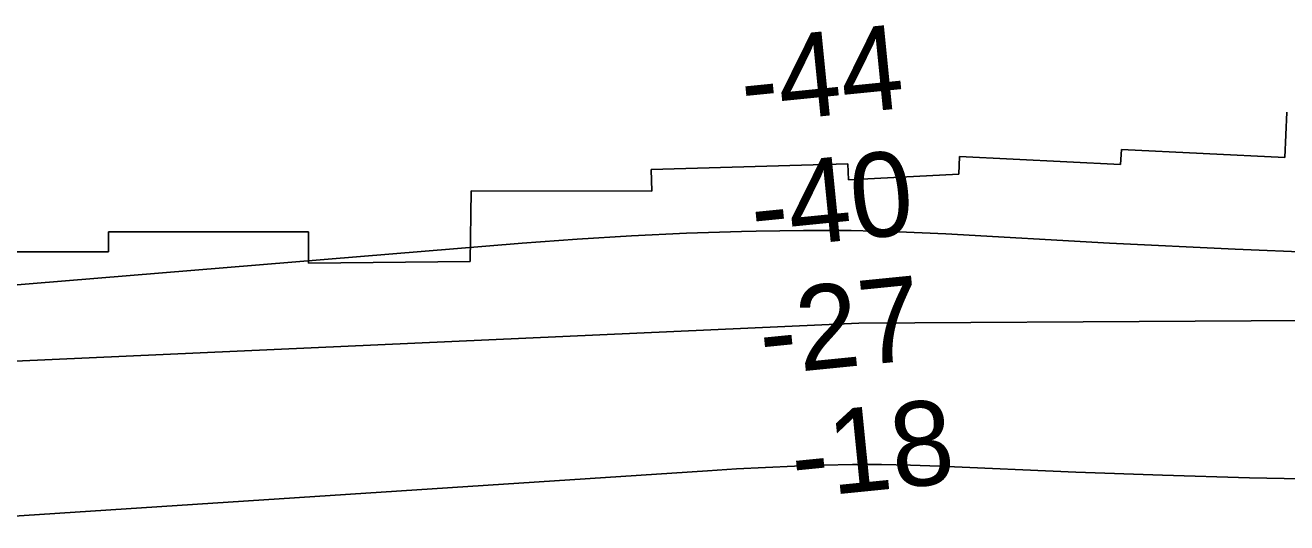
# Model space of a CAD drawing. Extents: x 3279314 to 3317160, y 734079 to 759431.
# Drawn here: x 3295369 to 3296371, y 752400 to 752796 of the extents above; entities that cross this region are included whole.
import ezdxf

# ---------------------------------------------------------------- set-up
doc = ezdxf.new("R2010")
doc.units = 0
for name, color, linetype in [('V-RIVR-RANG', 7, 'Continuous'), ('V-RRAP-RVMT', 7, 'Continuous'), ('V-TOPO-DPTH', 7, 'Continuous'), ('V-TOPO-MINR', 7, 'Continuous')]:
    doc.layers.add(name, color=color, linetype=linetype)

msp = doc.modelspace()

# ---------------------------------------------------------------- linework, layer by layer
at = {"layer": 'V-RRAP-RVMT'}
for p, q in [((3296369.1, 752690.4), (3296370.6, 752726.5)), ((3296238.6, 752685), (3296239.4, 752697)), ((3296239.4, 752697), (3296369.1, 752690.4)), ((3295866, 752681.1), (3296022.1, 752685.6)), ((3296022.1, 752685.6), (3296022.6, 752672.9)), ((3296110.2, 752677.4), (3296110.8, 752691.4)), ((3296110.8, 752691.4), (3296238.6, 752685)), ((3295866.5, 752663.8), (3295866, 752681.1)), ((3296022.6, 752672.9), (3296110.2, 752677.4)), ((3295722.3, 752608), (3295723, 752664)), ((3295723, 752664), (3295866.5, 752663.8)), ((3295435, 752631.4), (3295593.8, 752631.6)), ((3295435.1, 752615.6), (3295435, 752631.4)), ((3295593.8, 752631.6), (3295593.9, 752606.6)), ((3295288.8, 752615.8), (3295435.1, 752615.6)), ((3295593.9, 752606.6), (3295722.3, 752608))]:
    msp.add_line(p, q, dxfattribs=at)
at = {"layer": 'V-TOPO-DPTH'}
for p, q in [((3295807.1, 752625.6), (3295763.6, 752622.4)), ((3295807.1, 752625.6), (3295763.6, 752622.4)), ((3295850.5, 752628.3), (3295807.1, 752625.6)), ((3295850.5, 752628.3), (3295807.1, 752625.6)), ((3295894.1, 752630.3), (3295850.5, 752628.3)), ((3295894.1, 752630.3), (3295850.5, 752628.3)), ((3295937.6, 752631.8), (3295894.1, 752630.3)), ((3295937.6, 752631.8), (3295894.1, 752630.3)), ((3295949.4, 752632.1), (3295937.6, 752631.8)), ((3295949.4, 752632.1), (3295937.6, 752631.8)), ((3295987, 752632.6), (3295949.4, 752632.1)), ((3295987, 752632.6), (3295949.4, 752632.1)), ((3296024.7, 752632.5), (3295987, 752632.6)), ((3296024.7, 752632.5), (3295987, 752632.6)), ((3296062.3, 752631.5), (3296024.7, 752632.5)), ((3296062.3, 752631.5), (3296024.7, 752632.5)), ((3296100, 752629.8), (3296062.3, 752631.5)), ((3296100, 752629.8), (3296062.3, 752631.5)), ((3296229.9, 752622.5), (3296100, 752629.8)), ((3296229.9, 752622.5), (3296100, 752629.8)), ((3295763.6, 752622.4), (3295256.3, 752580.7)), ((3295763.6, 752622.4), (3295256.3, 752580.7)), ((3296329.6, 752617.6), (3296229.9, 752622.5)), ((3296329.6, 752617.6), (3296229.9, 752622.5)), ((3296429.3, 752613.5), (3296329.6, 752617.6)), ((3296429.3, 752613.5), (3296329.6, 752617.6))]:
    msp.add_line(p, q, dxfattribs=at)
for points in [[(3295213.8, 752522.2), (3296030.8, 752558.9), (3296831.9, 752563.6), (3297577.6, 752255.1)], [(3295213.8, 752522.2), (3296030.8, 752558.9), (3296831.9, 752563.6), (3297577.6, 752255.1)], [(3296409.9, 752434.9), (3296341, 752436.1), (3296272.1, 752438.1), (3296203.2, 752440.7), (3296094.8, 752445.5), (3296071.8, 752446.3), (3296048.8, 752446.7), (3296025.8, 752446.6), (3296002.8, 752446.2), (3295979.8, 752445.4), (3295956.8, 752444.4), (3295933.8, 752443.2), (3295910.8, 752441.8), (3295299, 752401.6)], [(3296409.9, 752434.9), (3296341, 752436.1), (3296272.1, 752438.1), (3296203.2, 752440.7), (3296094.8, 752445.5), (3296071.8, 752446.3), (3296048.8, 752446.7), (3296025.8, 752446.6), (3296002.8, 752446.2), (3295979.8, 752445.4), (3295956.8, 752444.4), (3295933.8, 752443.2), (3295910.8, 752441.8), (3295299, 752401.6)]]:
    msp.add_lwpolyline(points, dxfattribs=at)
at = {"layer": 'V-TOPO-MINR'}
for p, q in [((3295763.6, 752622.4), (3295807.1, 752625.6)), ((3295807.1, 752625.6), (3295850.5, 752628.3)), ((3295850.5, 752628.3), (3295894.1, 752630.3)), ((3295894.1, 752630.3), (3295937.6, 752631.8)), ((3295937.6, 752631.8), (3295949.4, 752632.1)), ((3295949.4, 752632.1), (3295987, 752632.6)), ((3295987, 752632.6), (3296024.7, 752632.5)), ((3296024.7, 752632.5), (3296062.3, 752631.5)), ((3296062.3, 752631.5), (3296100, 752629.8)), ((3296100, 752629.8), (3296229.9, 752622.5)), ((3295256.3, 752580.7), (3295763.6, 752622.4)), ((3296229.9, 752622.5), (3296329.6, 752617.6)), ((3296329.6, 752617.6), (3296429.3, 752613.5))]:
    msp.add_line(p, q, dxfattribs=at)
for points in [[(3295213.8, 752522.2), (3296030.8, 752558.9), (3296831.9, 752563.6), (3297577.6, 752255.1)], [(3295299, 752401.6), (3295910.8, 752441.8), (3295933.8, 752443.2), (3295956.8, 752444.4), (3295979.8, 752445.4), (3296002.8, 752446.2), (3296025.8, 752446.6), (3296048.8, 752446.7), (3296071.8, 752446.3), (3296094.8, 752445.5), (3296203.2, 752440.7), (3296272.1, 752438.1), (3296341, 752436.1), (3296409.9, 752434.9)]]:
    msp.add_lwpolyline(points, dxfattribs=at)

# ---------------------------------------------------------------- texts
at = {"layer": 'V-RIVR-RANG'}
for s, p in [('-44', (3295939.8, 752717.1)), ('-40', (3295947.9, 752617.4)), ('-27', (3295954.6, 752517.6)), ('-18', (3295980, 752419.7))]:
    msp.add_text(s, height=67, rotation=5.7123, dxfattribs=at).set_placement(p)

doc.saveas('drawing.dxf')
